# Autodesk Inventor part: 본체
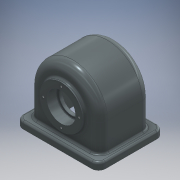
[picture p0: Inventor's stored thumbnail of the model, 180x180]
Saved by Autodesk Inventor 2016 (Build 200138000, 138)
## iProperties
Created: 2018-07
Part Number: 본체
Material: 철, 주조
Document SubType Name: Modeling
Designer: 201-27
Density: 7.15 g/cm^3
Appearance: 철 회색
Mass: 2410.14 g
Surface Area: 768.671 cm^2
Volume: 337.082 cm^3
Author: 201-27
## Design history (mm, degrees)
sketch "스케치1"
  geometry: L1 (-51, 0)-(51, 0); L2 (-51, 0)-(-51, 50); L3 (51, 0)-(51, 50); A1 r 51 centre (0, 50) between (51, 50) and (-51, 50); 2 further points
  constraints: 6 end point, 2 point on circle, 2 tangent, 2 vertical, 1 centre point, 1 coincident, 1 horizontal, 1 midpoint
  dimensions: "d1" = 50 distance of L1.start L2.end; "d2" = 102 distance of L1.start L1.end
extrude "돌출1" new body sketch "스케치1" stored distance "d3" = 74; taper "d4" = 0 deg
fillet "모깎기1" dims "d5" = 12
feature "쉘1" dims "d6" = 9
sketch "스케치2"
  geometry: L1 (-11, -10.5)-(89, -10.5); L2 (99, -0.5)-(99, 74.5); L3 (89, 84.5)-(-11, 84.5); L4 (-21, 74.5)-(-21, -0.5); L5 (-21, -10.5)-(99, 84.5); L6 (99, -10.5)-(-21, 84.5); L7 (0, 74)-(78, 74) reference; L8 (-12, 62)-(-12, 12) reference; L9 (78, 0)-(0, 0) reference; L10 (0, 65)-(78, 65) reference; L11 (81, 62)-(81, 12) reference; L12 (78, 9)-(0, 9) reference; L13 (-3, 12)-(-3, 62) reference; L14 (78, 0)-(0, 0) reference; L15 (90, 12)-(90, 62) reference; L16 (0, 74)-(78, 74) reference; L17 (-12, 62)-(-12, 12) reference; A1 r 10 centre (-11, 74.5) between (-11, 84.5) and (-21, 74.5); A2 r 10 centre (89, 74.5) between (99, 74.5) and (89, 84.5); A3 r 10 centre (89, -0.5) between (89, -10.5) and (99, -0.5); A4 r 10 centre (-11, -0.5) between (-21, -0.5) and (-11, -10.5); A5 r 12 centre (0, 62) between (0, 74) and (-12, 62) reference; A6 r 12 centre (0, 12) between (-12, 12) and (0, 0) reference; A7 r 3 centre (0, 62) between (0, 65) and (-3, 62) reference; A8 r 3 centre (78, 62) between (81, 62) and (78, 65) reference; A9 r 3 centre (78, 12) between (78, 9) and (81, 12) reference; A10 r 3 centre (0, 12) between (-3, 12) and (0, 9) reference; A11 r 12 centre (0, 12) between (-12, 12) and (0, 0) reference; A12 r 12 centre (78, 12) between (78, 0) and (90, 12) reference; A13 r 12 centre (78, 62) between (90, 62) and (78, 74) reference; A14 r 12 centre (0, 62) between (0, 74) and (-12, 62) reference; A15 r 12 centre (78, 12) between (78, 0) and (90, 12) reference; 1 further point
  constraints: 12 end point, 8 point on circle, 8 point on line, 8 tangent, 4 centre point, 3 equal radius, 2 midpoint, 2 parallel, 1 horizontal, 1 perpendicular
  dimensions: "d7" = 120 distance of L5.start L6.start; "d8" = 95 distance of L6.end L5.start; "d9" = 10 radius of A1
extrude "돌출2" join sketch "스케치2" distance "d10" = 10; taper "d11" = 0 deg
sketch "스케치3"
  geometry: L1 (50, 28)-(89, 28) reference; L2 (0, 28)-(50, 28) reference; L3 (50, 37)-(89, 37) reference; L4 (10, 37)-(50, 37) reference; L5 (50, -37)-(10, -37) reference; L6 (81, 22)-(50, 22); L7 (81, 22)-(81, 42); L8 (81, 42)-(50, 42); L9 (0, 0)-(101, 0); L10 (101, -25)-(101, 25) reference; L11 (50, 42)-(50, 22); L12 (0, -37.5)-(0, 37.5) reference; 3 further points
  constraints: 10 end point, 2 vertical, 1 midpoint, 1 perpendicular
  dimensions: "d13" = 6 distance between parallel lines of L1 L6; "d15" = 5 distance between parallel lines of L3 L8; "d17" = 50 distance between parallel lines of L12 L11; "d18" = 62 diameter of L7 L11
revolve "회전1" sketch "스케치3" stored, may be unused: angle "d19" = 90 deg
hole "구멍1" diameter "d22" = 29; stored, may be unused: countersink angle "d26" = 90 deg, drill point angle "d28" = 118 deg; dims "d23" = 6, "d24" = 35, "d25" = 15, "d27" = 8, "d74" = 10, "d75" = 10
sketch "스케치4"
  geometry: L1 (-50, -50)-(50, -50) reference; C1 r 31 at (0, 0) reference; 6 further points
  constraints: 1 midpoint, 1 vertical alignment, 5 other
  dimensions: "d31" = 26 distance of C1.centre point (0, 26); "d34" = 360 deg dimension on C1.centre point (0, 26) (derived)
hole "구멍2" sketch "스케치4" at (0, 26), (-26, 0), (0, -26), (26, 0) diameter "d36" = 3.242; stored, may be unused: countersink angle "d40" = 90 deg, drill point angle "d42" = 118 deg; dims "d37" = 8, "d38" = 21, "d39" = 15, "d41" = 10
fillet "모깎기2" dims "d43" = 3
chamfer "모따기1" distance "d44" = 1; stored, may be unused: second distance "d45" = 2, angle "d46" = 45 deg
hole "구멍3" diameter "d51" = 36; stored, may be unused: countersink angle "d55" = 90 deg, drill point angle "d57" = 118 deg; dims "d52" = 8, "d53" = 42, "d54" = 15, "d56" = 10, "d60" = 10, "d61" = 10
sketch "스케치6"
  geometry: C1 r 1.621 at (0, 26) reference; C2 r 31 at (0, 0) reference; 5 further points
  constraints: 1 coincident, 5 other
  dimensions: "d58" = 26 distance of point (0, 26) C2.centre (derived); "d65" = 360 deg dimension on C2.centre point (0, 26) (derived)
hole "구멍4" sketch "스케치6" at (0, 26), (-26, 0), (0, -26), (26, 0) diameter "d67" = 3.242; stored, may be unused: countersink angle "d71" = 90 deg, drill point angle "d73" = 118 deg; dims "d68" = 8, "d69" = 42, "d70" = 15, "d72" = 10
fillet "모깎기3" dims "d76" = 0.6
node "솔리드1"
mirror "대칭1"
node "투영된 루프1"
other parameters: "d16" = 62
